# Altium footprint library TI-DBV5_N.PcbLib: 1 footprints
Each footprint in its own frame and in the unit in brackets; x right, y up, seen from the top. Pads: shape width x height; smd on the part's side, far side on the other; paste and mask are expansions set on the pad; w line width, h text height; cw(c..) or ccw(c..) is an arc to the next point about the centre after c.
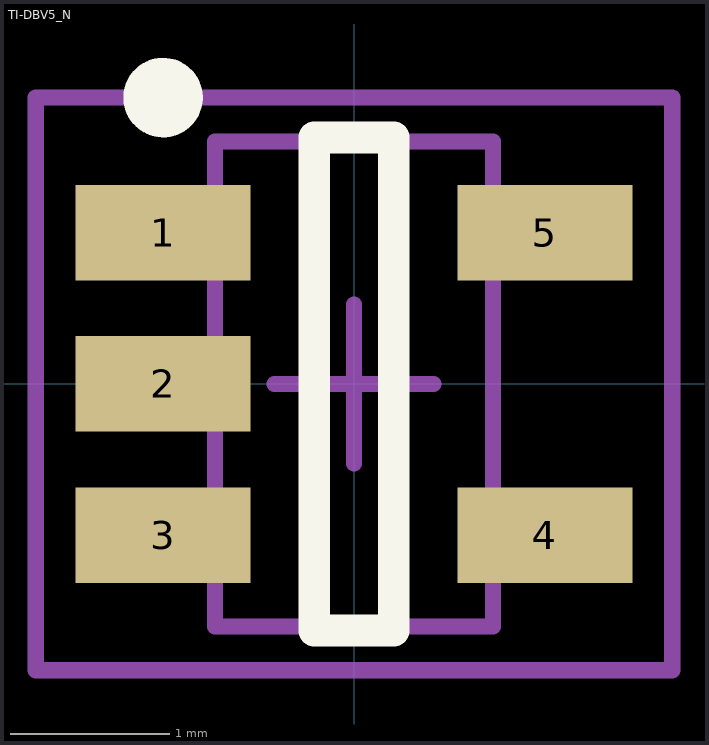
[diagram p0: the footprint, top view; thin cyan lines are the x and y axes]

## TI-DBV5_N [mm] "SOT23, 5-Leads, Body 2.9x1.6mm, Pitch 0.95mm, IPC Medium Density"
height 1.45
pads (5):
  rect 1.1x0.6 smd: 1(-1.2,0.95) 2(-1.2,0) 3(-1.2,-0.95) 4(1.2,-0.95) 5(1.2,0.95)
Top Overlay:
  circle w0.25: c-1.2,1.8 r0.125
  lines w0.2: -0.25,-1.55 0.25,-1.55 0.25,1.55 -0.25,1.55 -0.25,-1.55
Mechanical 13:
  lines w0.1: -0.875,-1.525 -0.875,1.525 0.875,1.525 0.875,-1.525 -0.875,-1.525
Mechanical 15:
  lines w0.05: -2,-1.8 -2,1.8 2,1.8 2,-1.8 -2,-1.8
  lines w0.1: -0.5,0 0.5,0 ; 0,-0.5 0,0.5
Mechanical 31:
  lines w0.102: -2,-1.8 -2,1.8 2,1.8 2,-1.8 -2,-1.8
  text ".Designator" at -1.651,0.635 h0.51
  text ".Comment" at -1.651,-0.127 h0.51
3D body "User Library-TPS79333DBVR.step": height 1.6, standoff -0.02, extent -1.513,-1.525 1.514,1.525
